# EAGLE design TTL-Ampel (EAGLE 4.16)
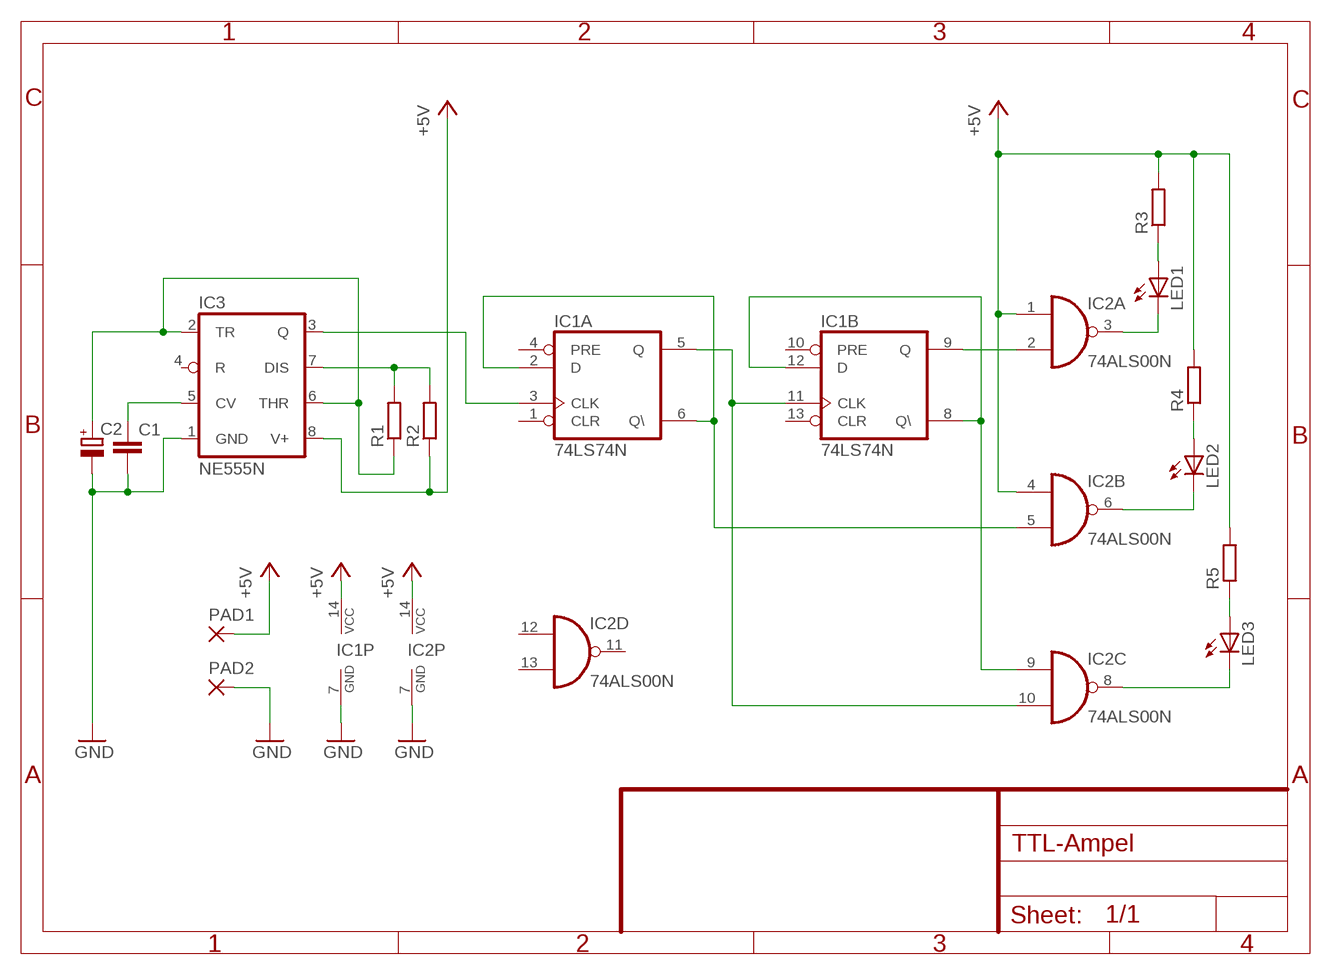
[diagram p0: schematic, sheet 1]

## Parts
C1  C-EU025-025X050  [C025-025X050]
C2  CPOL-EUE2.5-7  [E2,5-7]
IC1  74LS74N  [DIL14]
IC2  74ALS00N  [DIL14]
IC3  NE555N  [DIL08]
LED1  LED5MM  [LED5MM]
LED2  LED5MM  [LED5MM]
LED3  LED5MM  [LED5MM]
PAD1  2,54/1,0  [2,54/1,0]
PAD2  2,54/1,0  [2,54/1,0]
R1  R-EU_0207/10  [0207/10]
R2  R-EU_0207/10  [0207/10]
R3  R-EU_0207/10  [0207/10]
R4  R-EU_0207/10  [0207/10]
R5  R-EU_0207/10  [0207/10]

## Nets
+5V: IC1.14(P:VCC) IC2.1(A:I0) IC2.4(B:I0) IC2.14(P:VCC) IC3.8(V+) PAD1.1(P) R2.1 R3.2 R4.2 R5.2
GND: C1.2 C2.- IC1.7(P:GND) IC2.7(P:GND) IC3.1(GND) PAD2.1(P)
N$1: IC1.3(A:CLK) IC3.3(Q)
N$2: C2.+ IC3.2(TR) IC3.6(THR) R1.1
N$3: C1.1 IC3.5(CV)
N$4: IC3.7(DIS) R1.2 R2.2
N$6: IC1.2(A:D) IC1.6(A:Q\) IC2.5(B:I1)
N$7: IC1.8(B:Q\) IC1.12(B:D) IC2.9(C:I0)
N$8: IC1.5(A:Q) IC1.11(B:CLK) IC2.10(C:I1)
N$9: IC1.9(B:Q) IC2.2(A:I1)
N$10: IC2.3(A:O) LED1.K(C)
N$11: IC2.6(B:O) LED2.K(C)
N$12: IC2.8(C:O) LED3.K(C)
N$13: LED1.A R3.1
N$14: LED2.A R4.1
N$15: LED3.A R5.1
Unconnected: IC1.1(A:CLR) IC1.4(A:PRE) IC1.10(B:PRE) IC1.13(B:CLR) IC2.11(D:O) IC2.12(D:I0) IC2.13(D:I1) IC3.4(R)

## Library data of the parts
C1 = rcl:C-EU: CAPACITOR, European symbol
C2 = rcl:CPOL-EU: POLARIZED CAPACITOR, European symbol
IC1 = 74xx-eu:74*74: Dual D type positive edge triggered FLIP FLOP, preset and clear
IC2 = 74xx-eu:74*00: Quad 2-input NAND gate
IC3 = linear:*555: TIMER
LED1-LED3 = led:LED: LED
PAD1 PAD2 = wirepad:2,54/1,0: THROUGH-HOLE PAD
R1-R5 = rcl:R-EU_: RESISTOR, European symbol

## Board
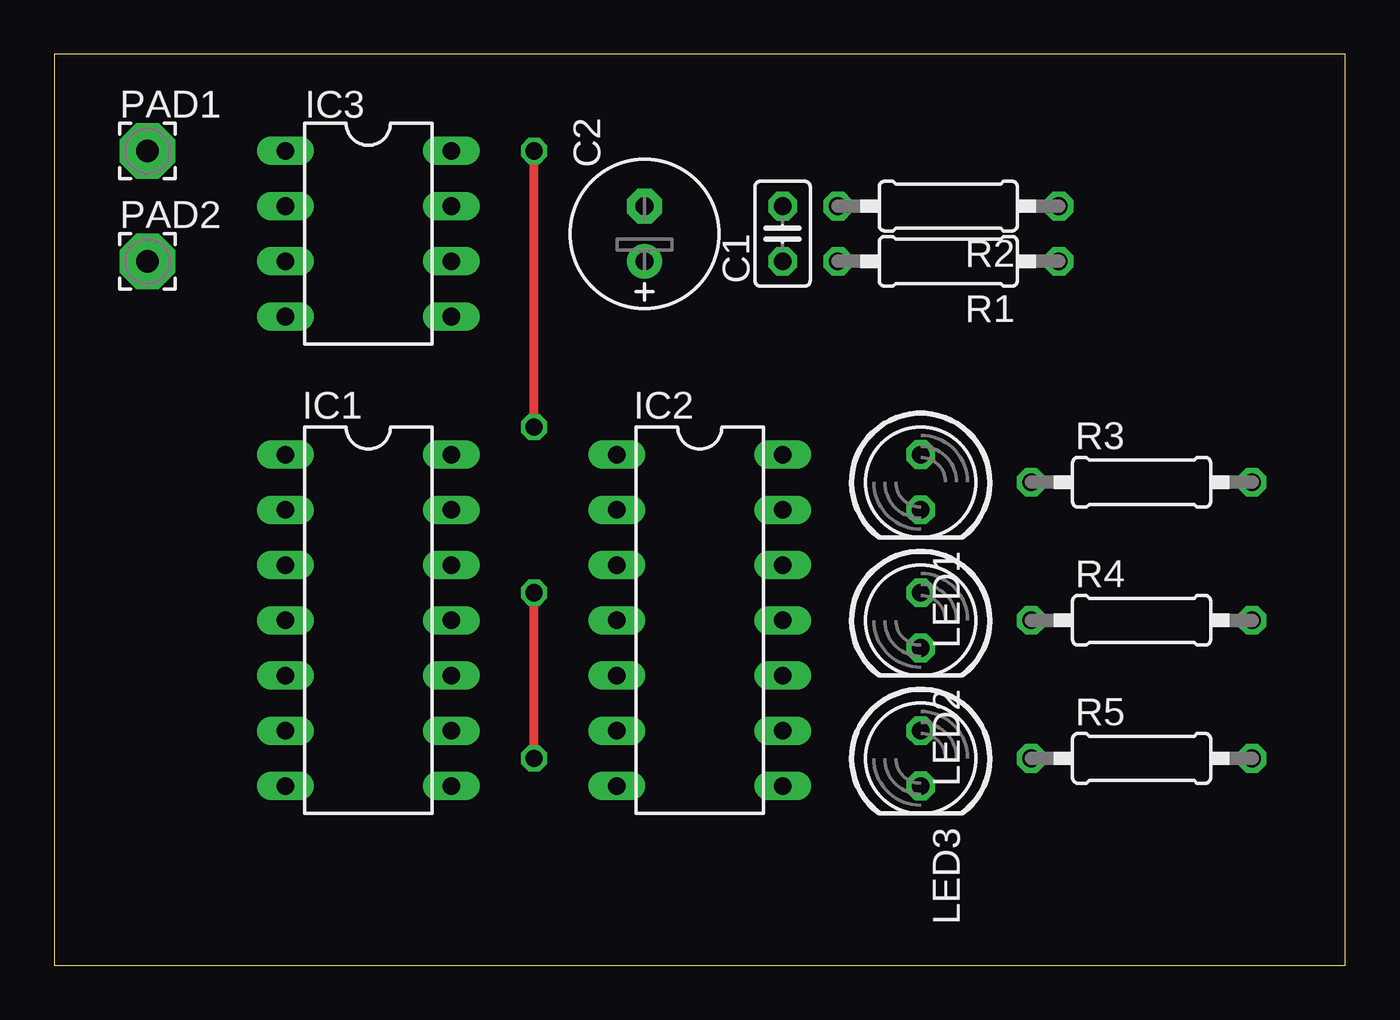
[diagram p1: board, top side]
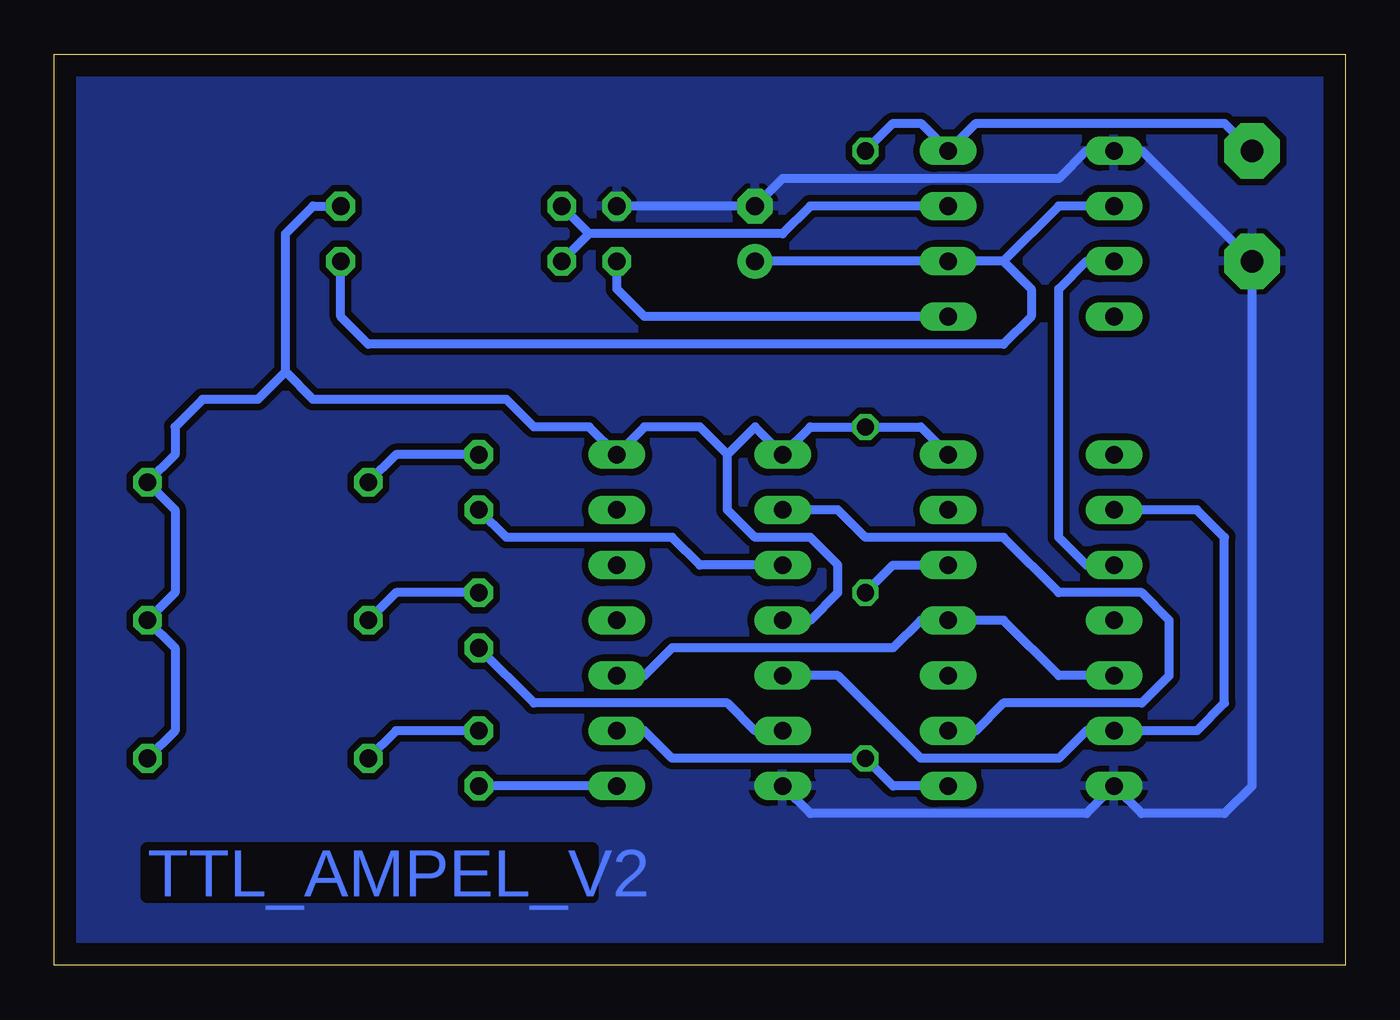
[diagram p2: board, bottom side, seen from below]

Size 59.36 x 41.9 mm. Coordinates in mm from the lower left corner, seen from the top.
Outline: 0,0 59.36,0 59.36,41.9 0,41.9 0,0
Copper layers (1*16): Top 0.035mm / dielectric 1.5mm / Bottom 0.035mm
Design rules "default": minimum track width 10mil, minimum drill 24mil, track to track 8mil, track to pad 8mil, pad to pad 8mil, via to via 8mil, smd to smd 8mil, copper to edge 40mil, drill to drill 8mil, minimum pad ring 10mil, minimum via ring 8mil, stop-mask expansion 4mil, vias tented up to drill 0mil, thermal gap 10mil

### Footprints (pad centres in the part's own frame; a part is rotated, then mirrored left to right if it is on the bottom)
C025-025X050 = drill 0.813 octagon: 1 -1.27,0; 2 1.27,0
E2,5-7 = drill 0.813 pad 1.6 round: + -1.27,0 | drill 0.813 pad 1.6 octagon: - 1.27,0
DIL14 = drill 0.813 long: 1 -7.62,-3.81; 2 -5.08,-3.81; 3 -2.54,-3.81; 4 0,-3.81; 5 2.54,-3.81; 6 5.08,-3.81; 7 7.62,-3.81; 8 7.62,3.81; 9 5.08,3.81; 10 2.54,3.81; 11 0,3.81; 12 -2.54,3.81; 13 -5.08,3.81; 14 -7.62,3.81
DIL08 = drill 0.813 long: 1 -3.81,-3.81; 2 -1.27,-3.81; 3 1.27,-3.81; 4 3.81,-3.81; 5 3.81,3.81; 6 1.27,3.81; 7 -1.27,3.81; 8 -3.81,3.81
LED5MM = drill 0.813 octagon: A -1.27,0; K 1.27,0
2,54/1,0 = drill 1.016 pad 2.54 octagon: 1 0,0
0207/10 = drill 0.813 octagon: 1 -5.08,0; 2 5.08,0

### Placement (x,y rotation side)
C1  33.49,33.65 90 top
C2  27.14,33.65 90 top
IC1  14.44,15.87 270 top
IC2  29.68,15.87 270 top
IC3  14.44,33.65 270 top
LED1  39.84,22.22 270 top
LED2  39.84,15.87 270 top
LED3  39.84,9.52 270 top
PAD1  4.28,37.46 0 top
PAD2  4.28,32.38 0 top
R1  41.11,32.38 180 top
R2  41.11,34.92 180 top
R3  50,22.22 0 top
R4  50,15.87 0 top
R5  50,9.52 0 top

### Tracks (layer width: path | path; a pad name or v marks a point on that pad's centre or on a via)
+5V  (via drill 0.8)
  Top 0.406: v22.06,24.76 v22.06,37.46
  Bottom 0.406: IC1.14 19.52,24.76 v22.06,24.76 24.6,24.76 IC2.1 27.14,24.76 28.41,23.49 | IC2.4 24.6,15.87 23.33,17.14 23.33,18.41 24.6,19.68 27.14,19.68 28.41,20.95 28.41,23.49 | 28.41,23.49 29.68,24.76 32.22,24.76 IC2.14 34.76,24.76 37.3,24.76 38.57,26.03 47.46,26.03 48.73,27.3 | 48.73,27.3 48.73,33.65 47.46,34.92 R2.1 | 48.73,27.3 50,26.03 52.54,26.03 53.81,24.76 53.81,23.49 R3.2 53.81,20.95 53.81,17.14 R4.2 53.81,14.6 53.81,10.79 R5.2 | PAD1.1 5.55,38.73 16.98,38.73 IC3.8 19.52,38.73 20.79,38.73 v22.06,37.46
GND
  Bottom 0.406: IC2.7 24.6,6.98 11.9,6.98 IC1.7 9.36,6.98 5.55,6.98 4.28,8.25 PAD2.1 9.36,37.46 IC3.1 11.9,37.46 13.17,36.19 25.87,36.19 C2.- C1.2
  pour Bottom (isolate 0.305): -2.07,43.81 61.43,43.81 61.43,-1.91 -2.07,-1.91
N$1
  Bottom 0.406: IC1.3 11.9,18.41 13.17,19.68 13.17,31.11 11.9,32.38 IC3.3
N$2
  Bottom 0.406: IC3.2 13.17,34.92 15.71,32.38 | 15.71,32.38 IC3.6 C2.+ | 15.71,32.38 14.44,31.11 14.44,29.84 15.71,28.57 44.92,28.57 46.19,29.84 R1.1
N$3
  Bottom 0.406: IC3.5 32.22,29.84 33.49,31.11 C1.1
N$4
  Bottom 0.406: IC3.7 24.6,34.92 25.87,33.65 34.76,33.65 | 34.76,33.65 R2.2 | 34.76,33.65 R1.2
N$6
  Bottom 0.406: IC1.2 6.82,20.95 5.55,19.68 5.55,12.06 6.82,10.79 IC1.6 11.9,10.79 13.17,9.52 19.52,9.52 23.33,13.33 IC2.5
N$7  (via drill 0.8)
  Top 0.406: v22.06,9.52 v22.06,17.14
  Bottom 0.406: IC2.9 32.22,10.79 30.95,9.52 v22.06,9.52 20.79,8.25 IC1.8 | v22.06,17.14 20.79,18.41 IC1.12
N$8
  Bottom 0.406: IC2.10 32.22,13.33 30.95,14.6 20.79,14.6 19.52,15.87 IC1.11 15.71,15.87 13.17,13.33 IC1.5
N$9
  Bottom 0.406: IC1.9 16.98,10.79 15.71,12.06 9.36,12.06 8.09,13.33 8.09,15.87 9.36,17.14 13.17,17.14 15.71,19.68 22.06,19.68 23.33,20.95 IC2.2
N$10
  Bottom 0.406: IC2.3 29.68,18.41 30.95,19.68 38.57,19.68 LED1.K
N$11
  Bottom 0.406: IC2.6 27.14,10.79 28.41,12.06 37.3,12.06 LED2.K
N$12
  Bottom 0.406: IC2.8 LED3.K
N$13
  Bottom 0.406: LED1.A 43.65,23.49 R3.1
N$14
  Bottom 0.406: LED2.A 43.65,17.14 R4.1
N$15
  Bottom 0.406: LED3.A 43.65,10.79 R5.1

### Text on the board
Bottom: TTL_AMPEL_V2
